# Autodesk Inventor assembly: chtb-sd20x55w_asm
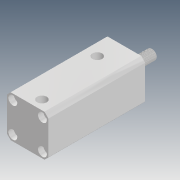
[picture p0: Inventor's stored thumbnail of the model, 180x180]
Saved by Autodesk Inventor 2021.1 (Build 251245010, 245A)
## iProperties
Company: Microsoft
Created: 2018-05
Part Number: chtb-sd20x55w_asm
Description: STEP AP214
Document SubType Name: Assembly
Designer: user
Title: chtb-sd20x55w_asm.STEP
Author: Windows
Revision Number: ÈÎºÎ
Sending System: SolidWorks 2015
Preprocessor: SwSTEP 2.0
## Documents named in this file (4)
- D:\Vault_2016\Projekty\Clamptek\Hydraulic\CHTB\CHTB-20\Inventor\CHTB-SD20x55W\chtb-sd20x55w_asm.iam
- D:\Vault_2016\Projekty\Clamptek\Hydraulic\CHTB\CHTB-20\Inventor\CHTB-SD20x55W\CHTB-SD20X55NBT.ipt
- D:\Vault_2016\Projekty\Clamptek\Hydraulic\CHTB\CHTB-20\Inventor\CHTB-SD20x55W\CHTB-SD20X55WHSG.ipt
- D:\Vault_2016\Projekty\Clamptek\Hydraulic\CHTB\CHTB-20\Inventor\CHTB-SD20x55W\QG.ipt
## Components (3 placed, 3 different names)
1. CHTB-SD20X55NBT_1
2. CHTB-SD20X55WHSG_2
3. QG_3
